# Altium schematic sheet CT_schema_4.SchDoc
size 400 x 230 mm
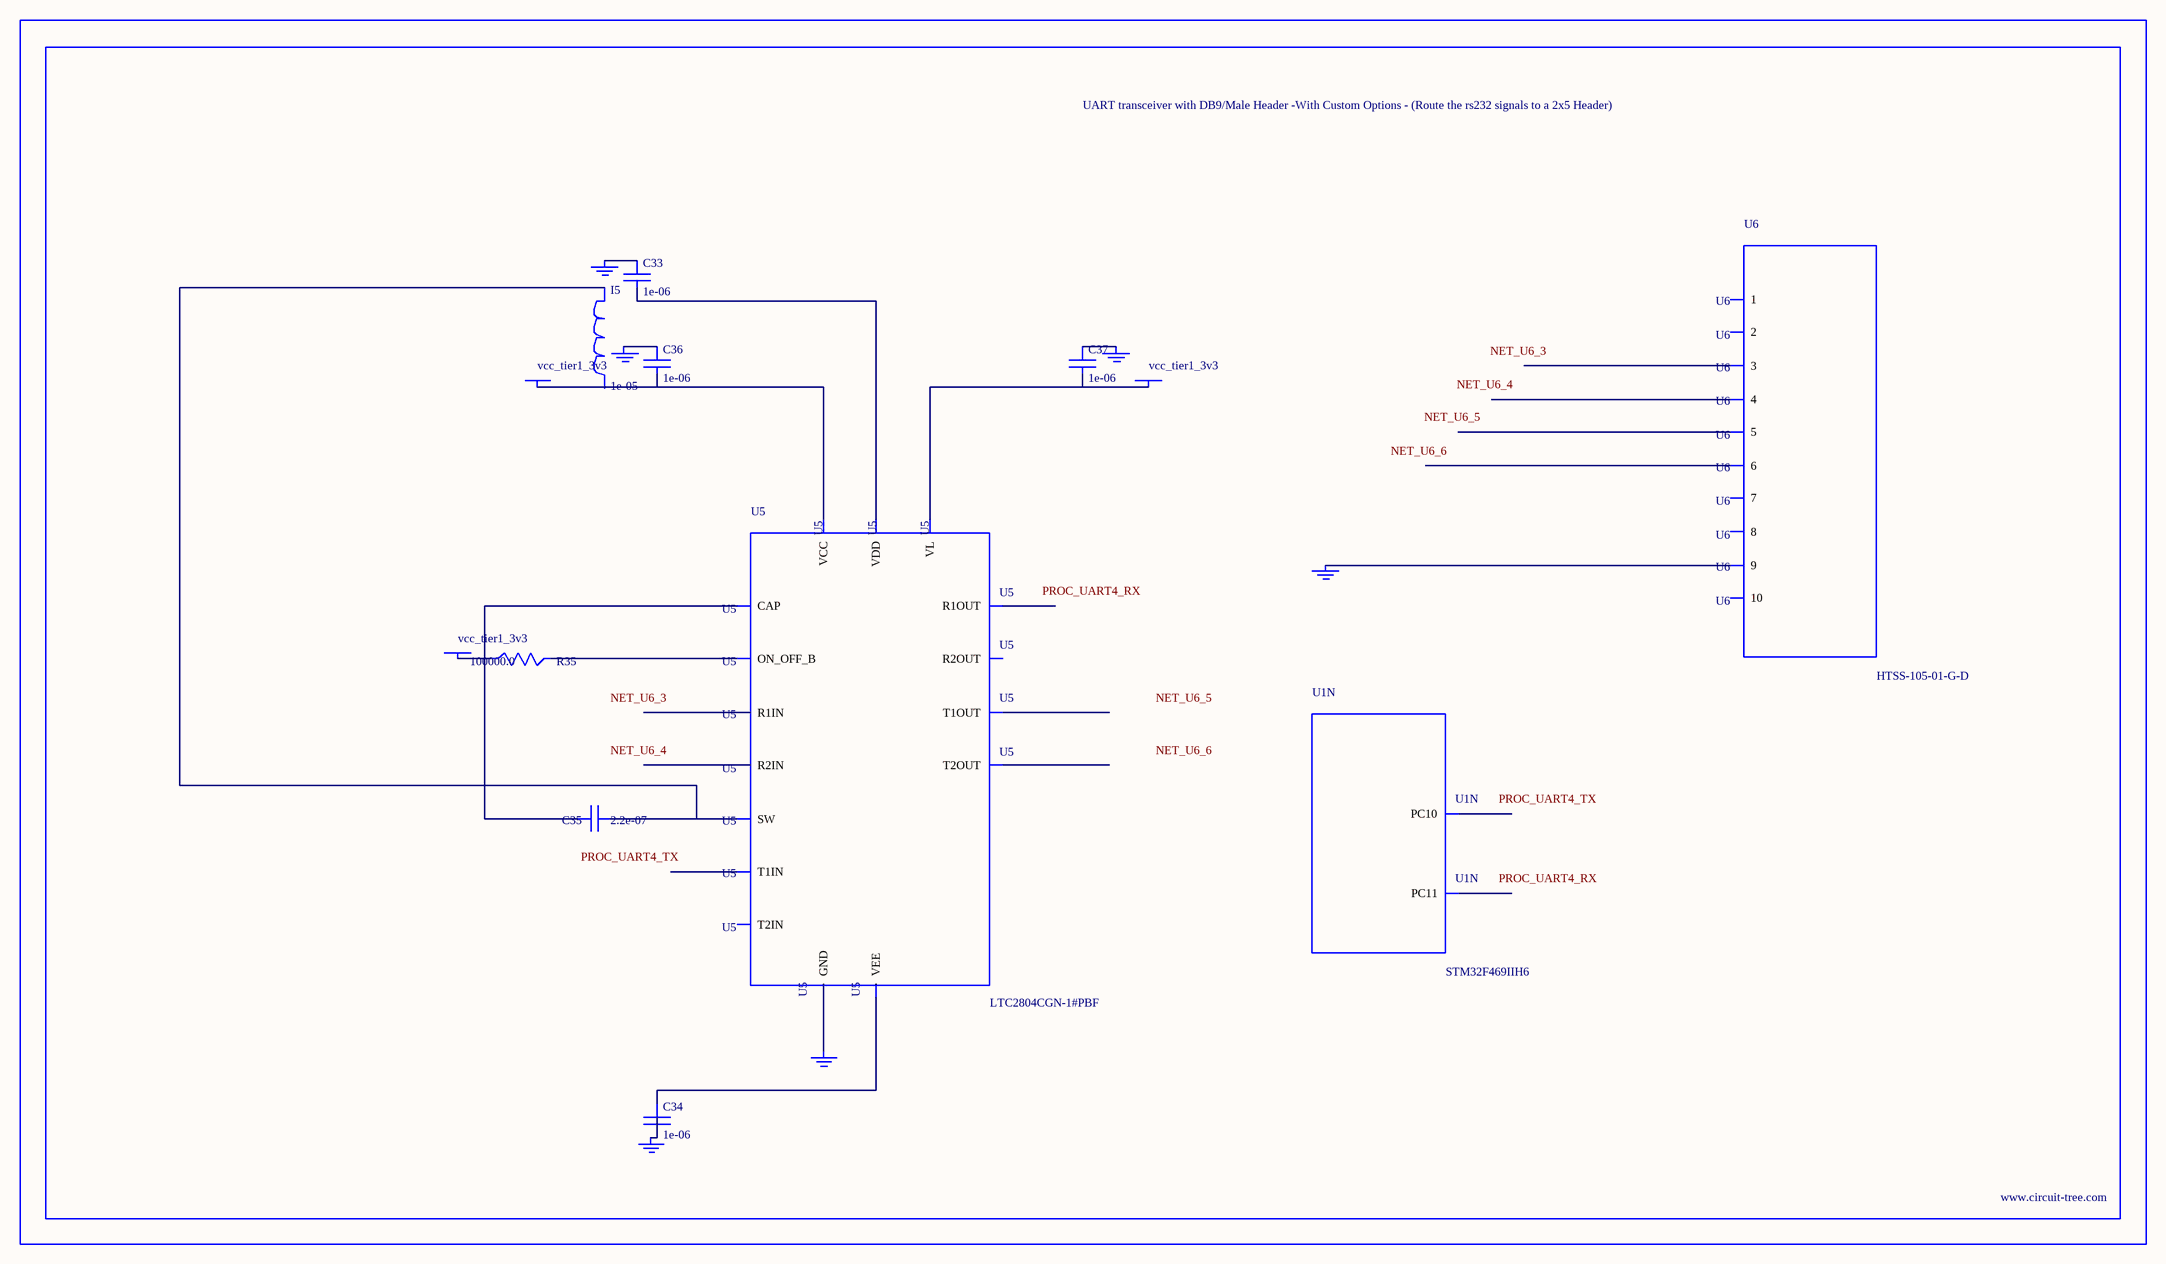
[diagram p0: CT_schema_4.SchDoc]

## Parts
BORDER3  (no value)
C33  1e-06  [C0603]
C34  1e-06  [C0603]
C35  2.2e-07  [C0603]
C36  1e-06  [C0603]
C37  1e-06  [C0603]
GND_INSTANCE_3_0  (no value)
GND_INSTANCE_3_1  (no value)
GND_INSTANCE_3_2  (no value)
GND_INSTANCE_3_3  (no value)
GND_INSTANCE_3_4  (no value)
GND_INSTANCE_3_5  (no value)
I5  1e-05  [L1210]
POWER_INSTANCE_3_0  vcc_tier1_3v3
POWER_INSTANCE_3_1  vcc_tier1_3v3
POWER_INSTANCE_3_2  vcc_tier1_3v3
R35  100000.0  [R0603]
U1  STM32F469IIH6  [UFBGA176]  (part N of 17)
U5  LTC2804CGN-1#PBF  [SSOP-16]
U6  HTSS-105-01-G-D  [HTSS-105-01-G-D]

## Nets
NetC33_1: C33.1 GND_INSTANCE_3_1.0(GND)
NetC33_2: C33.2 U5.6(VDD)
NetC34_1: C34.1 U5.9(VEE)
NetC34_2: C34.2 GND_INSTANCE_3_2.0(GND)
NetC35_1: C35.1 I5.1 U5.7(SW)
NetC35_2: C35.2 U5.10(CAP)
NetC36_1: C36.1 GND_INSTANCE_3_0.0(GND)
NetC36_2: C36.2 POWER_INSTANCE_3_0.0(PWR) U5.5(VCC)
NetC37_1: C37.1 GND_INSTANCE_3_3.0(GND)
NetC37_2: C37.2 POWER_INSTANCE_3_2.0(PWR) U5.12(VL)
NetGND_INSTANCE_3_4_0: GND_INSTANCE_3_4.0(GND) U5.8(GND)
NetGND_INSTANCE_3_5_0: GND_INSTANCE_3_5.0(GND) U6.9
NetPOWER_INSTANCE_3_1_0: POWER_INSTANCE_3_1.0(PWR) R35.1
NetR35_2: R35.2 U5.11(ON_OFF_B)

Not connected (* = marked no-connect by the designer): I5 2; U1 B13(PC11) B14(PC10); U5 1(R1IN) 2(R2IN) 3(T1OUT) 4(T2OUT) 13(T2IN) 14(T1IN) 15(R2OUT) 16(R1OUT); U6 1 2 3 4 5 6 7 8 10

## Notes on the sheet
- Labels drawn without touching a wire or pin: NET_U6_3, NET_U6_4, NET_U6_5, NET_U6_6, PROC_UART4_RX, PROC_UART4_TX

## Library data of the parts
BORDER3 = BORDER_PAGE3
C33 C34 C36 C37 = C0603C105K3RACTU
C35 = C0603C224K3RAC
GND_INSTANCE_3_0-GND_INSTANCE_3_5 = GND
I5 = CBC3225T100MR
POWER_INSTANCE_3_0-POWER_INSTANCE_3_2 = PWR
R35 = RC0603JR-07100KL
